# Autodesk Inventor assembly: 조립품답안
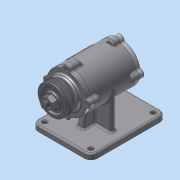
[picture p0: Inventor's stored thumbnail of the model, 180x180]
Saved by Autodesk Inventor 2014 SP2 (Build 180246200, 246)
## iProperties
Created: 2015-12
Part Number: 조립품답안
Document SubType Name: Assembly
Designer: 201-19
Author: 201-19
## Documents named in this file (11)
- C:\Users\201-19\Desktop\451207V1023\조립품답안.iam
- C:\Users\201-19\Desktop\451207V1023\본체.ipt
- C:\Users\201-19\Desktop\451207V1023\베어링 6204.ipt
- C:\Users\201-19\Desktop\451207V1023\축.ipt
- C:\Users\201-19\Desktop\451207V1023\키(4 x 4 x 12).ipt
- C:\Users\201-19\Desktop\451207V1023\V-벨트풀리.ipt
- C:\Users\201-19\Desktop\451207V1023\너트 M12x1.25.ipt
- C:\Users\201-19\Desktop\451207V1023\커버2.ipt
- C:\Users\201-19\Desktop\451207V1023\커버.ipt
- C:\Users\201-19\Desktop\451207V1023\볼트 M4 x 12.ipt
- C:\Users\201-19\Desktop\451207V1023\오일실.ipt
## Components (6 placed, 5 different names)
1. KS B 2023 6204 - 20 x 47 x 14:1
2. KS B 2023 6204 - 20 x 47 x 14:2
3. KS B 1311 (I) 4 x 4 x 12:1 — 각도:1
4. V-벨트풀리:1
5. KS B 1012 클래스 1 일반 - 미터 M12x1.25:1
6. KS B 2804 D D - 20 32 8:1
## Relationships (1: Angle 1)
- 각도:1 [Angle]: KS B 1311 (I) 4 x 4 x 12:1
